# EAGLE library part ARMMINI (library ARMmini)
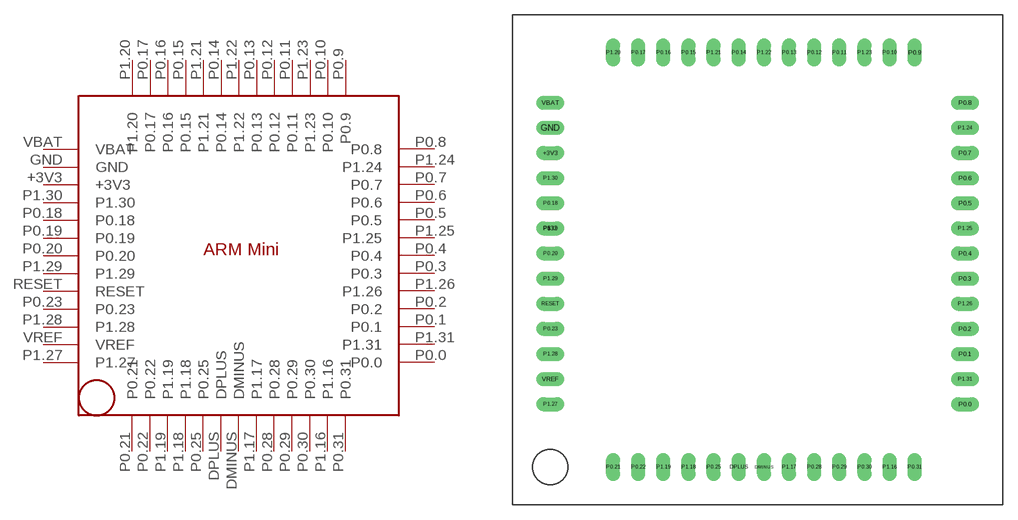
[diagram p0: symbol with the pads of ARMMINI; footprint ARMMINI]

Designator prefix -

## ARMMINI  [ARMMINI]
+3V3  +3V3  pwr
DMINUS  DMINUS
DPLUS  DPLUS
GND  GND  pwr
P0.0  P0.0
P0.1  P0.1
P0.2  P0.2
P0.3  P0.3
P0.4  P0.4
P0.5  P0.5
P0.6  P0.6
P0.7  P0.7
P0.8  P0.8
P0.9  P0.9
P0.10  P0.10
P0.11  P0.11
P0.12  P0.12
P0.13  P0.13
P0.14  P0.14
P0.15  P0.15
P0.16  P0.16
P0.17  P0.17
P0.18  P0.18
P0.19  P0.19
P0.20  P0.20
P0.21  P0.21
P0.22  P0.22
P0.23  P0.23
P0.25  P0.25
P0.28  P0.28
P0.29  P0.29
P0.30  P0.30
P0.31  P0.31
P1.16  P1.16
P1.17  P1.17
P1.18  P1.18
P1.19  P1.19
P1.20  P1.20
P1.21  P1.21
P1.22  P1.22
P1.23  P1.23
P1.24  P1.24
P1.25  P1.25
P1.26  P1.26
P1.27  P1.27
P1.28  P1.28
P1.29  P1.29
P1.30  P1.30
P1.31  P1.31
RESET  RESET
VBAT  VBAT
VREF  VREF

## Footprint ARMMINI (pad centres in mm)
drill 0.8 pad 1.422 long: +3V3 -6.35,35.56; DMINUS 15.24,3.81; DPLUS 12.7,3.81; GND -6.35,38.1; P0.0 35.56,10.16; P0.1 35.56,15.24; P0.2 35.56,17.78; P0.3 35.56,22.86; P0.4 35.56,25.4; P0.5 35.56,30.48; P0.6 35.56,33.02; P0.7 35.56,35.56; P0.8 35.56,40.64; P0.9 30.48,45.72; P0.10 27.94,45.72; P0.11 22.86,45.72; P0.12 20.32,45.72; P0.13 17.78,45.72; P0.14 12.7,45.72; P0.15 7.62,45.72; P0.16 5.08,45.72; P0.17 2.54,45.72; P0.18 -6.35,30.48; P0.19 -6.35,27.94; P0.20 -6.35,25.4; P0.21 0,3.81; P0.22 2.54,3.81; P0.23 -6.35,17.78; P0.25 10.16,3.81; P0.28 20.32,3.81; P0.29 22.86,3.81; P0.30 25.4,3.81; P0.31 30.48,3.81; P1.16 27.94,3.81; P1.17 17.78,3.81; P1.18 7.62,3.81; P1.19 5.08,3.81; P1.20 0,45.72; P1.21 10.16,45.72; P1.22 15.24,45.72; P1.23 25.4,45.72; P1.24 35.56,38.1; P1.25 35.56,27.94; P1.26 35.56,20.32; P1.27 -6.35,10.16; P1.28 -6.35,15.24; P1.29 -6.35,22.86; P1.30 -6.35,33.02; P1.31 35.56,12.7; RESET -6.35,20.32; VBAT -6.35,40.64; VREF -6.35,12.7
drill 0.8 long: P$32 -6.35,27.94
